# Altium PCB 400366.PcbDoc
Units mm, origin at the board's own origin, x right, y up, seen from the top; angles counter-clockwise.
Board outline 60.96 x 54.86 mm, 4 copper layers (Top Layer, Mid-Layer 1, Mid-Layer 2, Bottom Layer), stack 1.521 mm thick; 27 components, 35 nets, 218 pads, 513 vias.
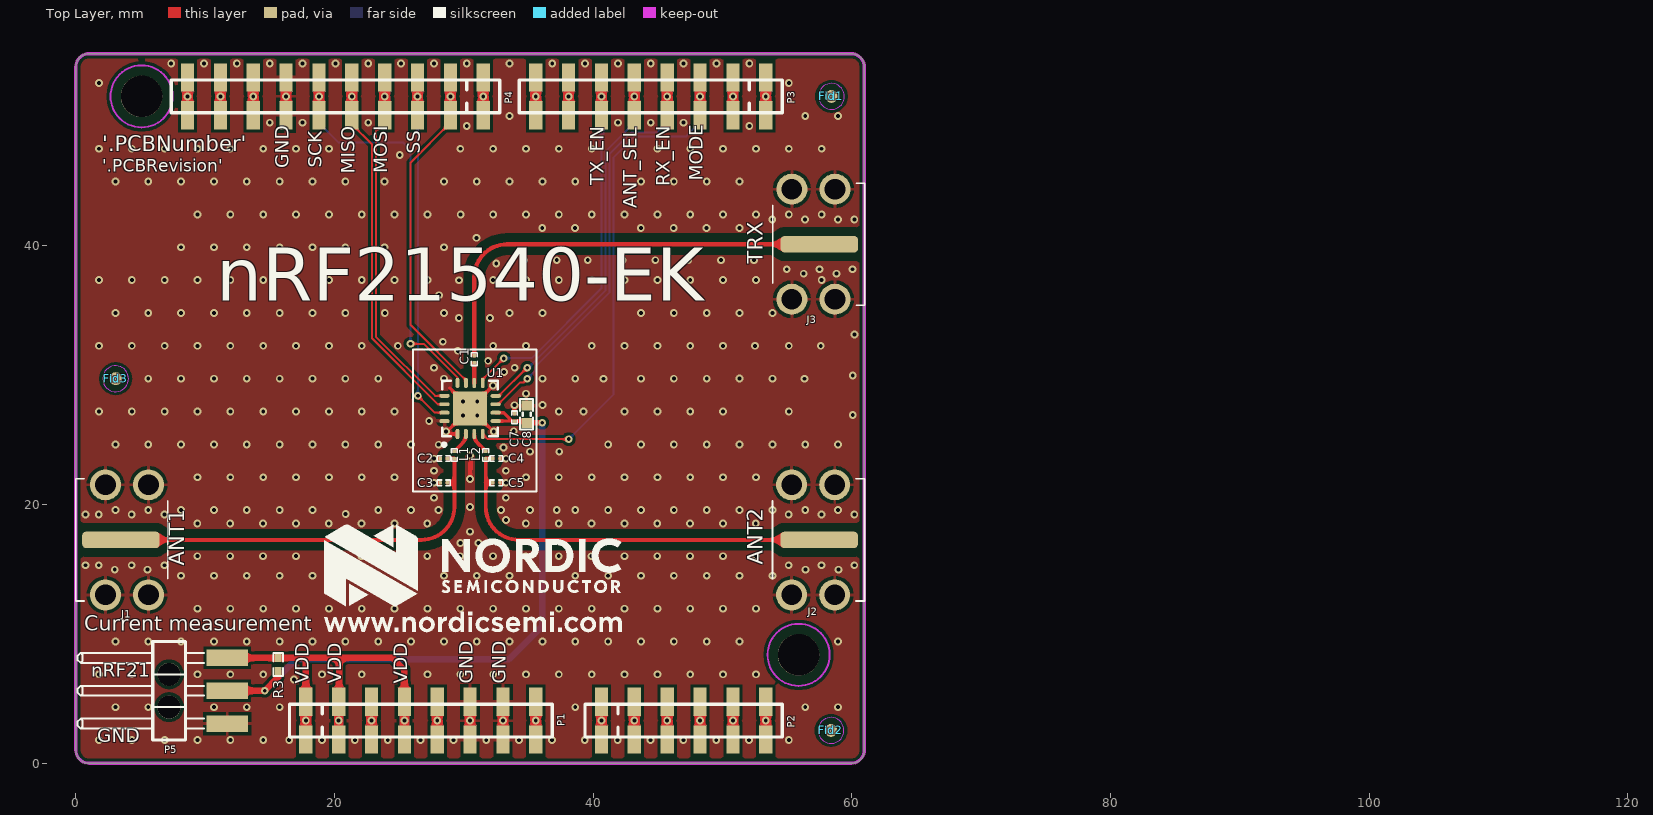
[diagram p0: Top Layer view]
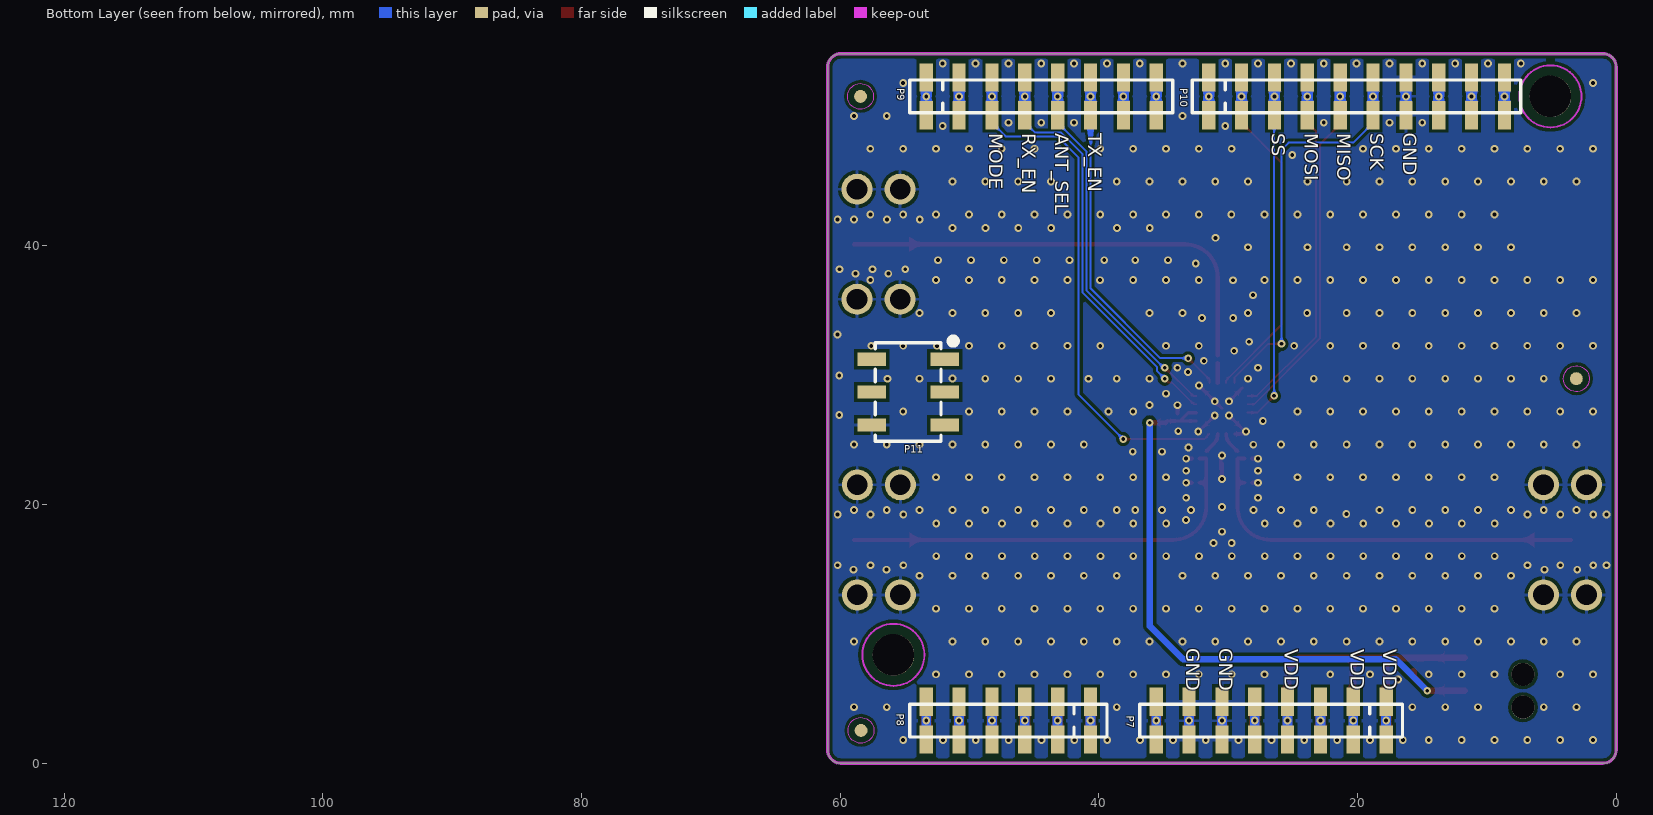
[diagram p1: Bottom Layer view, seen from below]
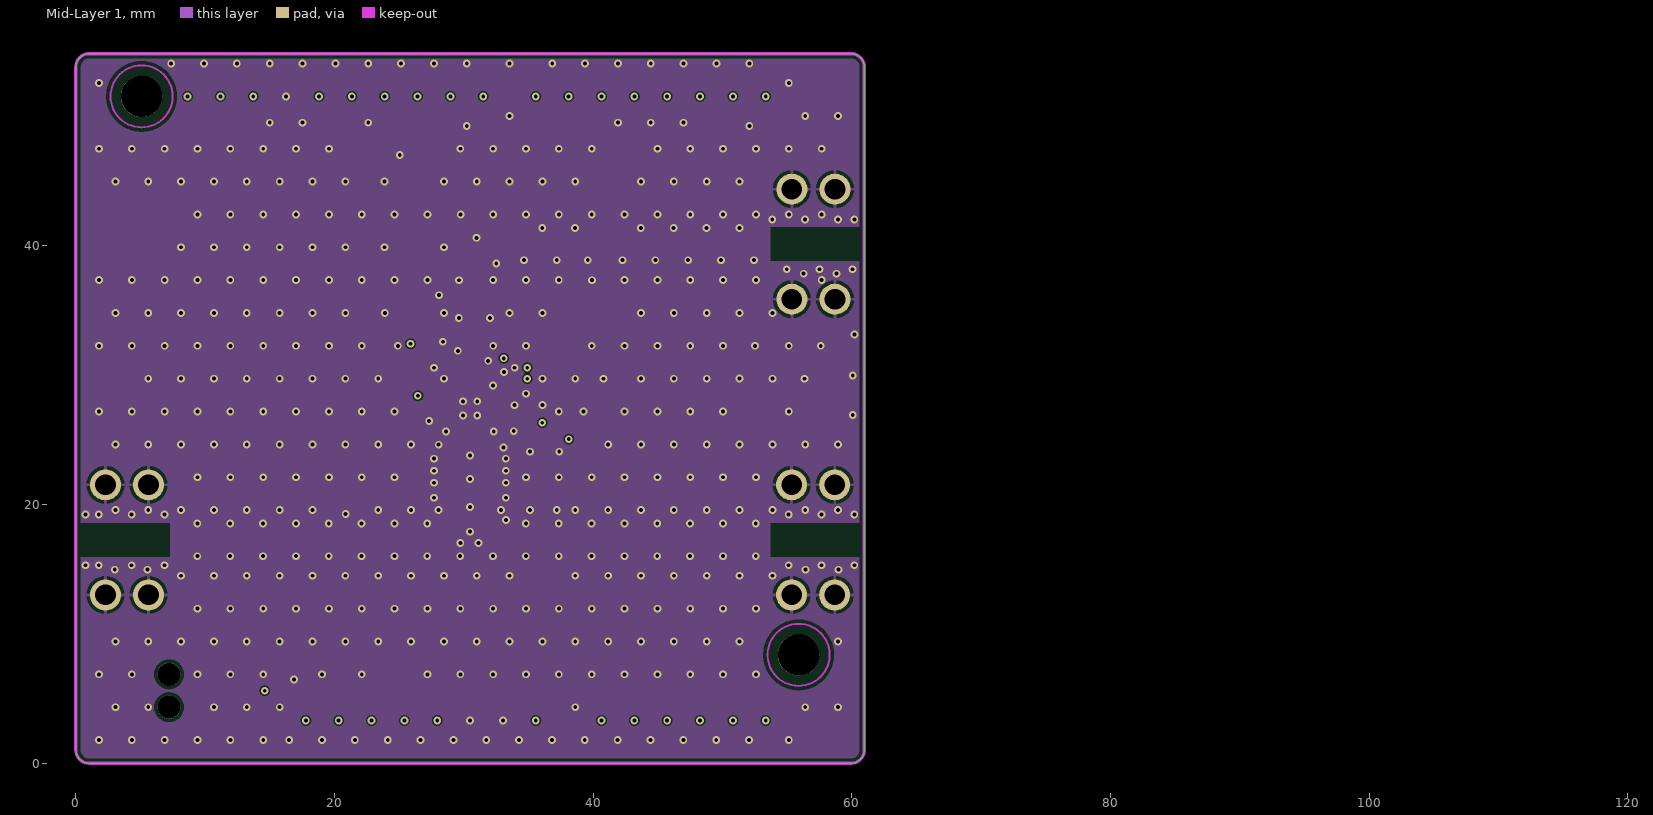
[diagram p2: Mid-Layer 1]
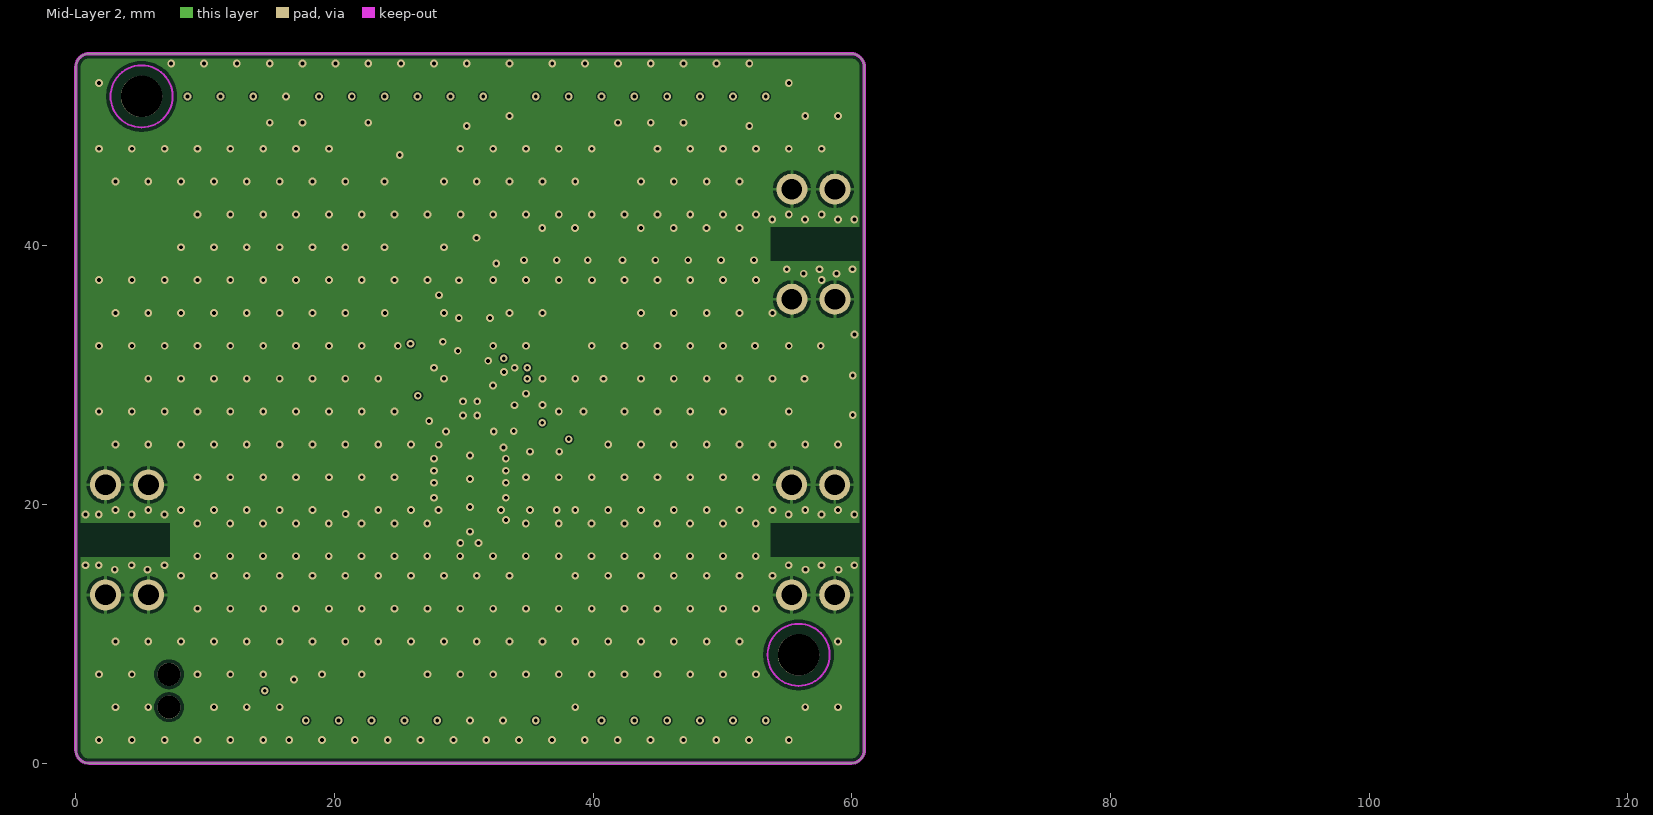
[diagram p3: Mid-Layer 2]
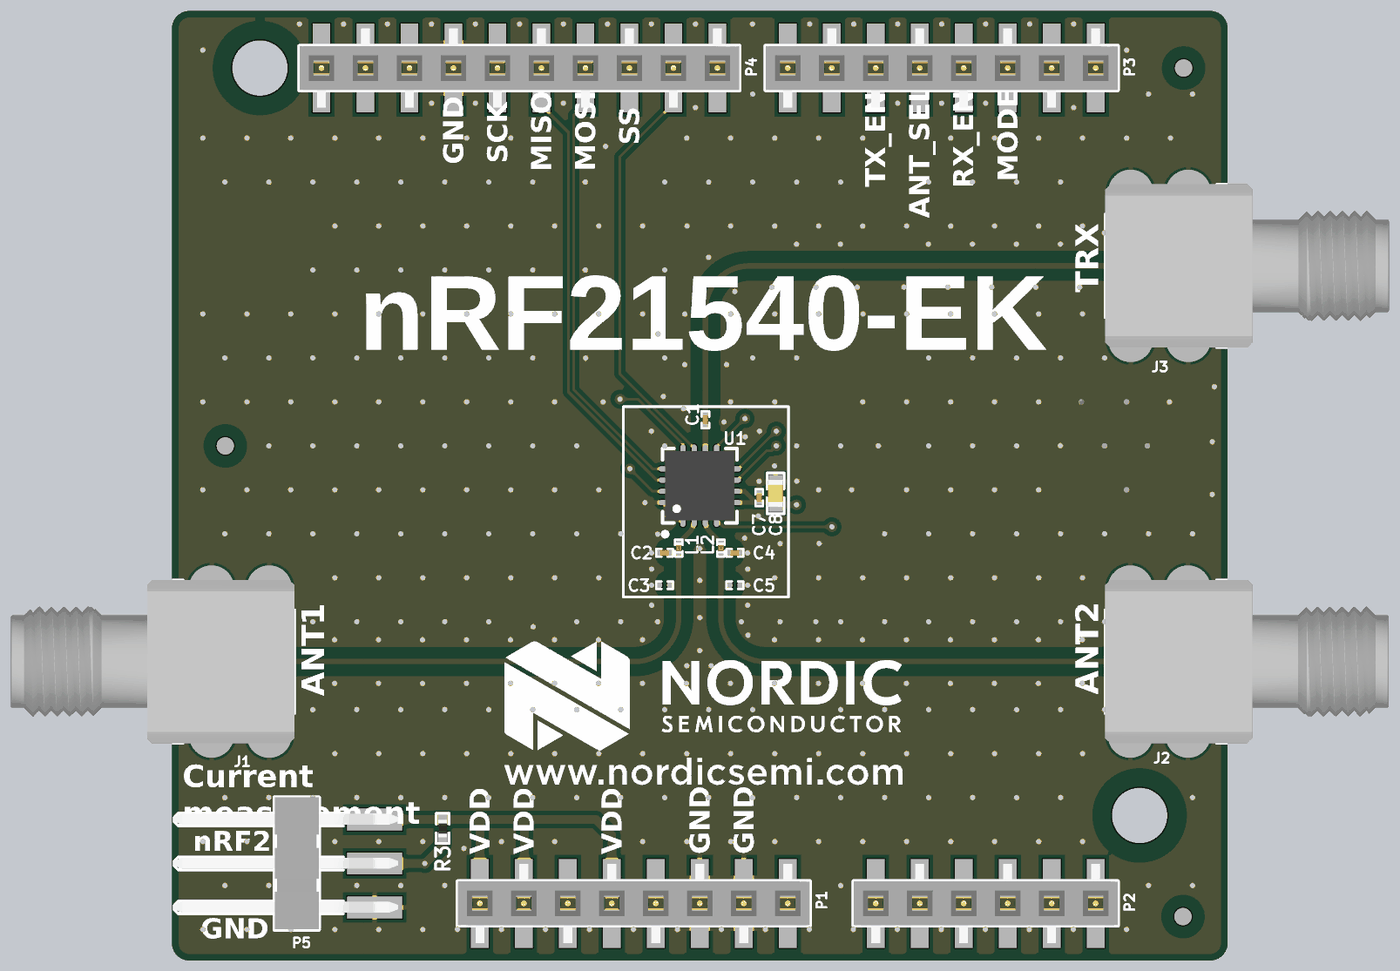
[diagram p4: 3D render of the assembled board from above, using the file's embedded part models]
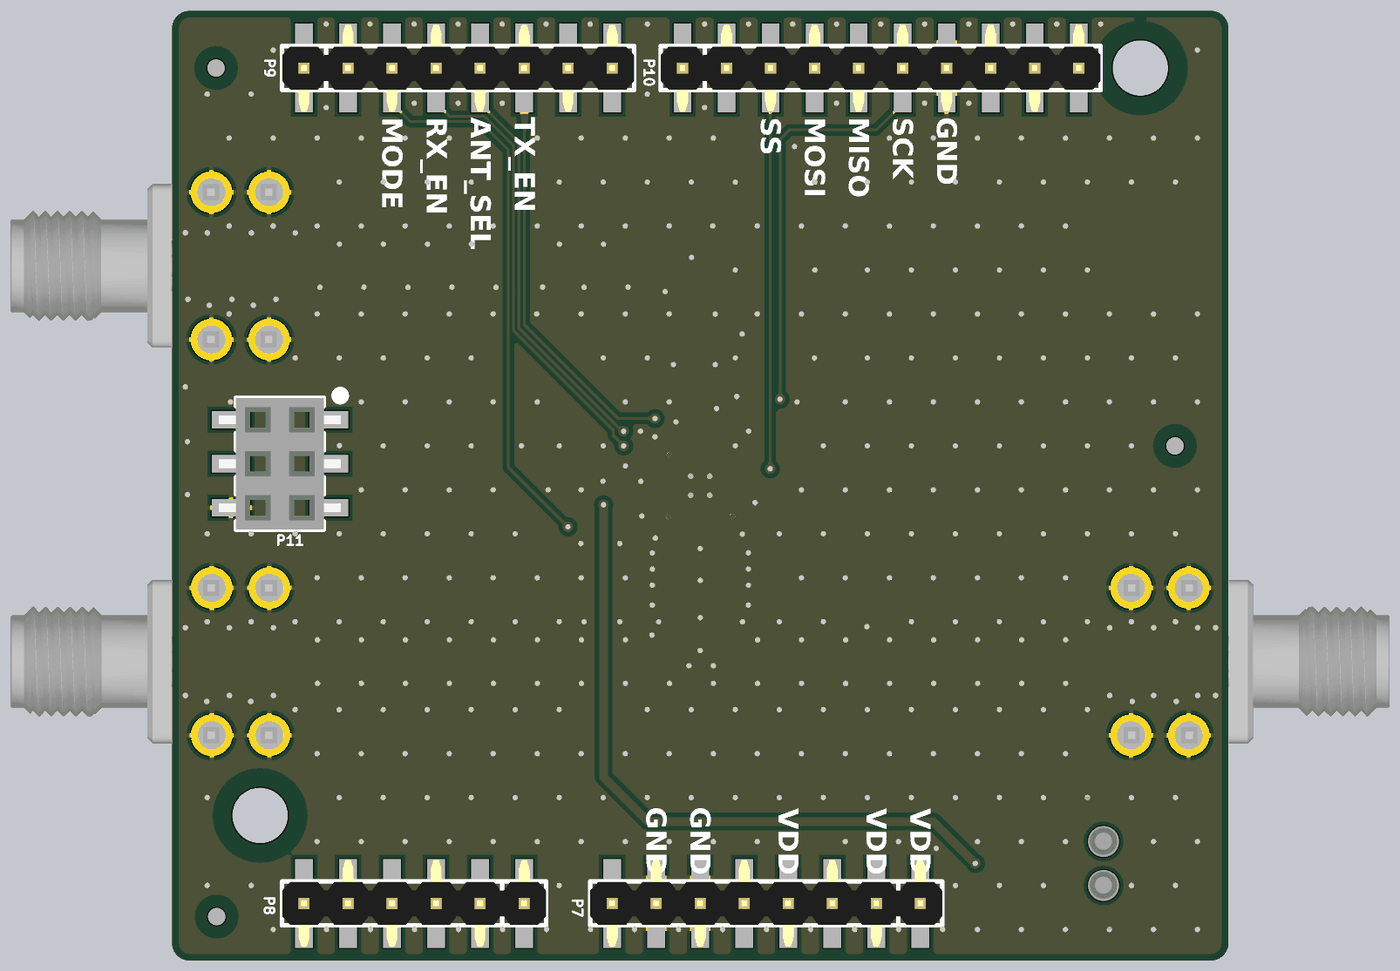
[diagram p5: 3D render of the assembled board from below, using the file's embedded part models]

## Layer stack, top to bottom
Top Solder: solder mask 0.043, SM-003, Dk 3.4
Top Layer: signal copper 0.045
Dielectric1: prepreg 0.166, FR-4, Dk 3.9
Mid-Layer 1: signal copper 0.035
Dielectric2: core 1.029, FR-4, Dk 3.9
Mid-Layer 2: signal copper 0.035
Dielectric3: prepreg 0.166, FR-4, Dk 3.9
Bottom Layer: signal copper 0.045
Bottom Solder: solder mask 0.043, SM-003, Dk 3.4

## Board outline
0,1.016 0,53.848 cw(c1.016,53.848) 1.016,54.864 59.944,54.864 cw(c59.944,53.848) 60.96,53.848 60.96,1.016 cw(c59.944,1.016) 59.944,0 1.016,0 cw(c1.016,1.016)

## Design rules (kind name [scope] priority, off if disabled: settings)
Clearance ANT_Clerance [InNet('ANT1') or InNet('ANT2') or InNet('TRX') or  InNet('RF_O1') or  InNet('RF_O2') or  InNet('RF_I') or  InNet('A') or  InNet('ANT') vs (InNamedPolygon('Top_Layer-GND')) or (InNamedPolygon('Bottom_Layer-GND')) or (InNamedPolygon('Mid_Layer_1-GND')) or (InNamedPolygon('Mid_Layer_2-GND'))] p1: gap=0.7 ignorepadtopadclearanceinfootprint=FALSE
Clearance ANT_Clerance_2 [InNet('ANT11') or  InNet('ANT21') vs (InNamedPolygon('Top_Layer-GND')) or (InNamedPolygon('Bottom_Layer-GND')) or (InNamedPolygon('Mid_Layer_1-GND')) or (InNamedPolygon('Mid_Layer_2-GND'))] p2: gap=0.5 ignorepadtopadclearanceinfootprint=FALSE
Clearance Polygon_Clearance [(InNamedPolygon('Top_Layer-GND')) or (InNamedPolygon('Bottom_Layer-GND')) or (InNamedPolygon('Mid_Layer_1-GND')) or (InNamedPolygon('Mid_Layer_2-GND'))] p3: gap=0.254 ignorepadtopadclearanceinfootprint=FALSE except(0: Arc-Hole Track-Hole SMDPad-Hole THPad-Hole Via-Hole Fill-Hole Poly-Hole Region-Hole Text-Hole)
Clearance [All] p4: gap=0.152 ignorepadtopadclearanceinfootprint=FALSE except(0: Arc-Hole Track-Hole SMDPad-Hole THPad-Hole Via-Hole Fill-Hole Poly-Hole Region-Hole Text-Hole)
ComponentClearance [All] p1 off: gap=0.254 collisioncheckmode=3 verticalgap=0.254 showdistances=FALSE
DiffPairsRouting [All] p1: maxlimit=0.254 minlimit=0.15 mostfreqgap=0.254 toplayer_maxgap=0.15 toplayer_prefgap=0.15 toplayer_minwidth=0.203 toplayer_maxwidth=0.381 toplayer_prefwidth=0.381 midlayer1_mingap=0.254 midlayer1_minwidth=0.203 midlayer1_maxwidth=0.381 midlayer1_prefwidth=0.381 midlayer2_mingap=0.254 midlayer2_minwidth=0.203 midlayer2_maxwidth=0.381 midlayer2_prefwidth=0.381 bottomlayer_maxgap=0.15 bottomlayer_prefgap=0.15 bottomlayer_minwidth=0.203 bottomlayer_maxwidth=0.381 bottomlayer_prefwidth=0.381 maxuncoupledlength=12.7
FabricationTestPointUsage TestPointUsage [All] p1: valid=0 allowmultiple=FALSE
FabricationTestpoint Testpoint [All] p1: side=3 testpointundercomponent=TRUE minsize=1.016 maxsize=2.54 preferedsize=1.524 minholesize=0 maxholesize=1.016 preferedholesize=0.813 testpointgrid=0.025 allowsidetop=TRUE allowsidebottom=TRUE usegrid=TRUE gridtolerance=0
Height [All] p1 off: minheight=0 maxheight=25.4 prefheight=12.7
HoleSize [All] p1: absolutevalues=TRUE maxlimit=5 minlimit=0.3 maxpercent=80.000 minpercent=20.000
MinimumAnnularRing [All] p1 off: minimumring=0.152
MinimumSolderMaskSliver [All] p1: minsoldermaskwidth=0.08
PolygonConnect PolygonConnect_1 [isVia and innet(gnd) or HasFootprint('COAXIAL-SWF')] p1: connectstyle=Direct reliefconductorwidth=0.254 reliefentries=4 polygonreliefangle="90 Angle" airgapwidth=0.254
PolygonConnect [All] p2: connectstyle=Relief reliefconductorwidth=0.254 reliefentries=4 polygonreliefangle="90 Angle" airgapwidth=0.254
RoutingVias [All] p1: holewidth=0.305 width=0.61 viastyle="Through Hole" minholewidth=0.3 minwidth=0.6 maxholewidth=0.711 maxwidth=1.27
SilkToSilkClearance [All] p1: silktosilkclearance=0
SilkToSolderMaskClearance SilkscreenOverComponentPads [IsPad] p1: minsilkscreentomaskgap=0.254 clearancetoexposedcopper=TRUE
SolderMaskExpansion [All] p1: expansion=0.076 istentingtop=FALSE
Width [All] p1: maxlimit=2.54 minlimit=0.152 preferedwidth=0.152
21 further rules are at their usual default settings.

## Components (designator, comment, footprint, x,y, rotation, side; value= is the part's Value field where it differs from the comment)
C1 "1.0pF" CAPC0603X03L_C#1 30.805,31.242 r270 top
C2 "1.2pF" CAPC0603X03L_C#2 28.445,23.557 r0 top
C3 "N.C." CAPC0603X03L_C_NC 28.445,21.684 r0 top
C4 "1.2pF" CAPC0603X03L_C#2 32.508,23.557 r180 top
C5 "N.C." CAPC0603X03L_C_NC 32.508,21.684 r180 top
C7 "100nF" CAPC0603X03L_C#1 33.909,26.747 r270 top
C8 "10µF" CAPC1608X06L 34.857,26.989 r270 top
Fid1 "Fiducial mark" Fiducial 58.42,51.562 r0 top
Fid2 "Fiducial mark" Fiducial 58.385,2.54 r0 top
Fid3 "Fiducial mark" Fiducial 3.08,29.733 r270 top
J1 "SMA_2081005-1" SMA_2081005-1 3.95,17.272 r0 top locked
J2 "SMA_2081005-1" SMA_2081005-1 57.007,17.272 r180 top locked
J3 "SMA_2081005-1" SMA_2081005-1 57.025,40.132 r180 top locked
L1 "1.9nH" INDC0603X03L_C 29.266,23.831 r270 top
L2 "1.9nH" INDC0603X03L_C 31.694,23.831 r270 top
P1 "Socket 1x8" SOCKET_1x8_SMD 17.78,3.302 r0 top locked
P2 "Socket 1x6" SOCKET_1x6_SMD 40.64,3.302 r0 top locked
P3 "Socket 1x8" SOCKET_1x8_SMD 53.34,51.562 r180 top locked
P4 "Socket 1x10" SOCKET_1x10_SMD 31.496,51.562 r180 top locked
P5 "Pin List 1x3, Angled" LIST_ANG_1x3-SMD-2.54MM 11.7,5.607 r270 top locked
P7 "Pin List 1x8" LIST_1x8_SMD 17.78,3.302 r0 bottom locked
P8 "Pin List 1x6" LIST_1x6_SMD 40.64,3.302 r0 bottom locked
P9 "Pin List 1x8" LIST_1x8_SMD 53.34,51.562 r180 bottom locked
P10 "Pin List 1x10" LIST_1x10_SMD 31.496,51.562 r180 bottom locked
P11 "Socket 2x3" SOCKET_2x3_SMD-2.54mm-bottom 54.737,28.702 r270 top locked
R3 "0R" RESC1005X04L 15.635,7.632 r90 top
U1 "nRF21540-QDAA" QFN65P400X400X65_HS-17N 30.48,27.432 r90 top

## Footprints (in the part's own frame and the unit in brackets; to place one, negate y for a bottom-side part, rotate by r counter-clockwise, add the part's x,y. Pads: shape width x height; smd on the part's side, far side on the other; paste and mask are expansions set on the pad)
CAPC0603X03L_C#1 [mm] "Chip Capacitor, 2-Leads, Body 0.6x0.3mm, IPC High Density"
  rect 0.27x0.3 smd: 1(-0.285,0) 2(0.285,0)
  silkscreen extent -0.49,-0.22 0.49,0.22, body extent -0.3,-0.15 0.31,0.15, height 0.3
CAPC0603X03L_C#2 [mm] "Chip Capacitor, 2-Leads, Body 0.6x0.3mm, IPC High Density"
  rrect50% 0.27x0.3 smd: 1(-0.285,0) 2(0.285,0)
  silkscreen extent -0.49,-0.22 0.49,0.22, body extent -0.3,-0.15 0.31,0.15, height 0.3
CAPC0603X03L_C_NC [mm] "Chip Capacitor, 2-Leads, Body 0.6x0.3mm, IPC High Density"
  rrect50% 0.27x0.3 smd: 1(-0.285,0) 2(0.285,0)
  silkscreen extent -0.49,-0.22 0.49,0.22
CAPC1608X06L [mm] "Chip Capacitor, 2-Leads, Body 1.6x0.8mm, IPC High Density"
  rect 0.75x0.8 smd: 1(-0.675,0) 2(0.675,0)
  silkscreen extent -1.17,-0.5 1.17,0.5, body extent -0.8,-0.43 0.8,0.43, height 0.8
Fiducial [mm] "Fiducial Mark"
  round 1 smd: 0(0,0)
  round 1 smd far side: 0(0,0)
  Top Layer keep-out circle w0.01: c0,0 r1
  Bottom Layer keep-out circle w0.01: c0,0 r1
INDC0603X03L_C [mm] "Chip Inductor, 2-Leads, Body 0.6x0.3mm, IPC High Density"
  rrect50% 0.27x0.3 smd: 1(-0.285,0) 2(0.285,0)
  silkscreen extent -0.49,-0.22 0.49,0.22, body extent -0.31,-0.16 0.31,0.16, height 0.26
LIST_1x6_SMD [mm] "Pin List, 2.54mm, SMD"
  rect 1.02x2.19 smd: 1(0,-1.465) 1(0,1.465) 2(2.54,-1.465) 2(2.54,1.465) 3(5.08,-1.465) 3(5.08,1.465) 4(7.62,-1.465) 4(7.62,1.465) 5(10.16,-1.465) 5(10.16,1.465) 6(12.7,-1.465) 6(12.7,1.465)
  silkscreen extent -1.27,-1.27 13.97,1.27, body extent -1.27,-2.5 13.97,2.5, height 9.82
LIST_1x8_SMD [mm] "Pin List, 2.54mm, SMD"
  rect 1.02x2.19 smd: 1(0,-1.465) 1(0,1.465) 2(2.54,-1.465) 2(2.54,1.465) 3(5.08,-1.465) 3(5.08,1.465) 4(7.62,-1.465) 4(7.62,1.465) 5(10.16,-1.465) 5(10.16,1.465) 6(12.7,-1.465) 6(12.7,1.465) 7(15.24,-1.465) 7(15.24,1.465) 8(17.78,-1.465) 8(17.78,1.465)
  silkscreen extent -1.27,-1.27 19.05,1.27, body extent -1.27,-2.5 19.05,2.5, height 9.82
LIST_1x10_SMD [mm] "Pin List, 2.54mm, SMD"
  rect 1.02x2.19 smd: 1(0,-1.465) 1(0,1.465) 2(2.54,-1.465) 2(2.54,1.465) 3(5.08,-1.465) 3(5.08,1.465) 4(7.62,-1.465) 4(7.62,1.465) 5(10.16,-1.465) 5(10.16,1.465) 6(12.7,-1.465) 6(12.7,1.465) 7(15.24,-1.465) 7(15.24,1.465) 8(17.78,-1.465) 8(17.78,1.465) 9(20.32,-1.465) 9(20.32,1.465) 10(22.86,-1.465) 10(22.86,1.465)
  silkscreen extent -1.27,-1.27 24.13,1.27, body extent -1.27,-2.5 24.13,2.5, height 9.82
LIST_ANG_1x3-SMD-2.54MM [mm] "Pin List, 2.54mm, Surface Mount, Angled"
  round 1.78 hole 1.78 unplated: 0(-1.27,-4.496) 0(1.27,-4.496)
  rect 1.27x3.18 smd: 1(-2.54,0) 2(0,0) 3(2.54,0)
  silkscreen extent -3.81,-11.58 3.81,-1.8, body extent -3.83,-11.61 3.79,1.35, height 3.03
QFN65P400X400X65_HS-17N [mm] "QFN, 16-Leads, Body 4.00x4.00mm, Pitch 0.65mm, Thermal Pad 2.65x2.65mm, IPC Medium Density"
  oval 0.8x0.3 smd: 1(-1.975,0.975) 2(-1.975,0.325) 3(-1.975,-0.325) 4(-1.975,-0.975) 9(1.975,-0.975) 10(1.975,-0.325) 11(1.975,0.325) 12(1.975,0.975)
  oval 0.3x0.8 smd: 5(-0.975,-1.975) 6(-0.325,-1.975) 7(0.325,-1.975) 8(0.975,-1.975) 13(0.975,1.975) 14(0.325,1.975) 15(-0.325,1.975) 16(-0.975,1.975)
  rect 2.65x2.65 smd: 17(0,0)
  silkscreen extent -2.92,-2.15 2.15,2.15, body extent -2,-2 2,2, height 0.65
RESC1005X04L [mm] "Chip Resistor, 2-Leads, Body 1.0x0.5mm, IPC High Density"
  rect 0.6x0.55 smd: 1(-0.5,0) 2(0.5,0)
  silkscreen extent -0.87,-0.38 0.88,0.38, body extent -0.5,-0.25 0.5,0.25, height 0.3
SMA_2081005-1 [mm] "SMA, Right Angle, Board Edge, TH/SMT mount, 50Ohm"
  round 2.6 on Top Paste: 0(-1.665,-4.255) 0(-1.665,4.255) 0(1.665,-4.255) 0(1.665,4.255)
  rrect50% 6x1.27 smd: 1(-0.465,0)
  round 2.4 hole 1.6: 2(-1.665,-4.255) 2(-1.665,4.255) 2(1.665,-4.255) 2(1.665,4.255)
  silkscreen extent -3.97,-4.72 3.15,4.72, body extent -13.25,-4.72 3.13,4.72, height 6.37
SOCKET_1x6_SMD [mm] "Socket, 2.54mm, SMD"
  rect 1.02x2.19 smd: 1(0,-1.465) 1(0,1.465) 2(2.54,-1.465) 2(2.54,1.465) 3(5.08,-1.465) 3(5.08,1.465) 4(7.62,-1.465) 4(7.62,1.465) 5(10.16,-1.465) 5(10.16,1.465) 6(12.7,1.465) 6(12.7,-1.465)
  silkscreen extent -1.27,-1.27 13.97,1.27, body extent -1.27,-2.29 13.97,2.29, height 7.47
SOCKET_1x8_SMD [mm] "Socket, 2.54mm, SMD"
  rect 1.02x2.19 smd: 1(0,-1.465) 1(0,1.465) 2(2.54,-1.465) 2(2.54,1.465) 3(5.08,-1.465) 3(5.08,1.465) 4(7.62,-1.465) 4(7.62,1.465) 5(10.16,-1.465) 5(10.16,1.465) 6(12.7,1.465) 6(12.7,-1.465) 7(15.24,-1.465) 7(15.24,1.465) 8(17.78,-1.465) 8(17.78,1.465)
  silkscreen extent -1.27,-1.27 19.05,1.27, body extent -1.27,-2.29 19.05,2.29, height 7.47
SOCKET_1x10_SMD [mm] "Socket, 2.54mm, SMD"
  rect 1.02x2.19 smd: 1(0,1.465) 1(0,-1.465) 2(2.54,-1.465) 2(2.54,1.465) 3(5.08,-1.465) 3(5.08,1.465) 4(7.62,-1.465) 4(7.62,1.465) 5(10.16,-1.465) 5(10.16,1.465) 6(12.7,-1.465) 6(12.7,1.465) 7(15.24,-1.465) 7(15.24,1.465) 8(17.78,-1.465) 8(17.78,1.465) 9(20.32,-1.465) 9(20.32,1.465) 10(22.86,-1.465) 10(22.86,1.465)
  silkscreen extent -1.27,-1.27 24.13,1.27, body extent -1.27,-2.29 24.13,2.29, height 7.47
SOCKET_2x3_SMD-2.54mm-bottom [mm] "Socket, 2.54mm, SMD"
  rect 1.02x2.22 smd far side: 1(-2.54,-2.825) 2(-2.54,2.825) 3(0,-2.825) 4(0,2.825) 5(2.54,-2.825) 6(2.54,2.825)
  body extent -3.81,-3.52 3.81,3.52, height 7.47

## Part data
C1: library part C0201-1p0, "CAP CER 1PF 25V C0G/NP0 0201", Manufacturer=Murata, Manufacturer Part Number=GJM0335C1E1R0BB01D, Part number IPS=N.A., Supplier Part Number 1=490-11172-1-ND
C2 C4: library part C0201-1.2p, "Chip Cap 0201", Part number IPS=N.A.
C3 C5: library part C0201-N.C., "Not mounted", Part number IPS=N.A.
C7: library part C0201-100n, "Capacitor, X5R, ±10%", Part number IPS="00000001248, 00000002505"
C8: library part C0603-10µ, "Capacitor, X5R, ±20%", Part number IPS=00000007785
Fid1 Fid2 Fid3: library part Fid-Mark, "Fiducial Mark", Part number IPS=N.A.
J1 J2 J3: library part SMA_RA_EDGE_SMT, "SMA, Female, Right Angle, TH/SMT, 50Ohm, Board Edge", Manufacturer=CompuPack, Manufacturer Part Number=ARFRBE22029-GGP, Part number IPS=N.A., Supplier Part Number 1=C-Q1911001
L1 L2: library part L0201-1n9-HQ-Murata, "Inductor, 600mA, ±0.1ｎH, 120mOhm", Manufacturer=Murata, Manufacturer Part Number=LQP03HQ1N9B02, Part number IPS=N.A., Supplier Part Number 1=490-13889-1-ND
P1 P3: library part "Socket 1x8 SMD", "Socket 1x8, 2.54mm (100mil), SMD", Manufacturer=W-CON, Manufacturer Part Number=2171-108MS0CUNR1, Part number IPS=00000009963
P2: library part "Socket 1x6 SMD", "Socket 1x6, 2.54mm (100mil), SMD", Manufacturer=W-CON, Manufacturer Part Number=2171-106MS0CUNR1, Part number IPS=00000009964
P4: library part "Socket 1x10 SMD", "Socket 1x10, 2.54mm (100mil), SMD", Manufacturer=W-CON, Manufacturer Part Number=2171-110MS0CUNR1, Part number IPS=00000009965
P5: library part "Pin List Ang 1x3 SMD, 2.54mm", "Pin List 1x3, 2.54mm (100mil), Right Angled, SMD", Manufacturer=W-CON, Manufacturer Part Number=1125B-1103S0Z135R2, Part number IPS=00000009971
P7 P9: library part "Pin List 1x8 SMD", "Pin List 1x8, 2.54mm (100mil), SMD", Manufacturer=W-CON, Manufacturer Part Number=1125-1108S0M116R2, Part number IPS=N.A.
P8: library part "Pin List 1x6 SMD", "Pin List 1x6, 2.54mm (100mil), SMD", Manufacturer=W-CON, Manufacturer Part Number=1125-1106S0M116R2, Part number IPS=N.A.
P10: library part "Pin List 1x10 SMD", "Pin List 1x10, 2.54mm (100mil), SMD", Manufacturer=W-CON, Manufacturer Part Number=1125-1110S0M116R2, Part number IPS=N.A.
P11: library part "Socket 2x3 SMD Bottom", "Socket 2x3, 2.54mm (100mil), SMD", Manufacturer=W-CON, Manufacturer Part Number=2171-203MS0CUNR1, Part number IPS=N.A.
R3: library part R0402-0R, "Resistor, ±5%, 0.063W", Part number IPS=00000007128, Supplier Part Number 1=146-9661
U1: "Radio front-end / range extender for 2.4GHz", Manufacturer="Nordic Semiconductor", Part number IPS=N.A.

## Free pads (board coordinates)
  round 3.2 hole 3.2 unplated: 1(5.08,51.562) 1(55.88,8.382)
  round 0.3 on Mech16: 1(117.207,34.156) 1(118.957,35.906) 1(118.957,36.406) 1(118.957,36.906) 1(118.957,37.406) 1(118.957,37.906) 1(118.957,38.407)

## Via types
v1: diameter 0.6, hole 0.3, Top Layer to Bottom Layer, tented both sides, 513 vias

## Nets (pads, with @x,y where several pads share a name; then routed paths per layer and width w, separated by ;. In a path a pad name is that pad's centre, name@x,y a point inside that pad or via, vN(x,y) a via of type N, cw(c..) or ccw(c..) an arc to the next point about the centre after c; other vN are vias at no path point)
A0: P2.1 P8.1 | length 5.9
  Top Layer w0.762: P2.1@40.64,1.837 P2.1@40.64,4.767
  Bottom Layer w0.762: P8.1@40.64,1.837 v1(40.64,3.302) P8.1@40.64,4.767
A1: P2.2 P8.2 | length 5.9
  Top Layer w0.762: P2.2@43.18,1.837 P2.2@43.18,4.767
  Bottom Layer w0.762: P8.2@43.18,1.837 v1(43.18,3.302) P8.2@43.18,4.767
A2: P2.3 P8.3 | length 5.9
  Top Layer w0.762: P2.3@45.72,1.837 P2.3@45.72,4.767
  Bottom Layer w0.762: P8.3@45.72,1.837 v1(45.72,3.302) P8.3@45.72,4.767
A3: P2.4 P8.4 | length 5.9
  Top Layer w0.762: P2.4@48.26,1.837 P2.4@48.26,4.767
  Bottom Layer w0.762: P8.4@48.26,1.837 v1(48.26,3.302) P8.4@48.26,4.767
A4: P2.5 P8.5 | length 5.9
  Top Layer w0.762: P2.5@50.8,1.837 P2.5@50.8,4.767
  Bottom Layer w0.762: P8.5@50.8,1.837 v1(50.8,3.302) P8.5@50.8,4.767
A5: P2.6 P8.6 | length 5.9
  Top Layer w0.762: P2.6@53.34,1.837 P2.6@53.34,4.767
  Bottom Layer w0.762: P8.6@53.34,1.837 v1(53.34,3.302) P8.6@53.34,4.767
ANT1: L1.1 U1.2 | length 1.7
  Top Layer w0.28: L1.1 29.835,24.685 ccw(c29.063,25.457) U1.2
ANT2: L2.1 U1.3 | length 1.7
  Top Layer w0.28: U1.3 ccw(c31.896,25.457) 31.125,24.685 L2.1
ANT_SEL: P3.5 P9.5 U1.8 | length 32.2
  Top Layer w0.152: U1.8 32.705,28.407 34.88,30.582 v1(34.901,30.582)
  Top Layer w0.762: P3.5@43.18,50.097 P3.5@43.18,53.027
  Bottom Layer w0.152: v1(34.901,30.582) 34.991,30.582 40.945,36.536 40.945,47.295 43.18,49.53 P9.5@43.18,50.097
  Bottom Layer w0.762: P9.5@43.18,50.097 P9.5@43.18,53.027
  other v1: 43.18,51.562
AREF: P4.8 P10.8 | length 5.9
  Top Layer w0.762: P4.8@13.716,50.097 P4.8@13.716,53.027
  Bottom Layer w0.762: P10.8@13.716,50.097 P10.8@13.716,53.027
  other v1: 13.716,51.562
"D0 (RX)": P3.1 P9.1 | length 5.9
  Top Layer w0.762: P3.1@53.34,50.097 P3.1@53.34,53.027
  Bottom Layer w0.762: P9.1@53.34,50.097 P9.1@53.34,53.027
  other v1: 53.34,51.562
"D1 (TX)": P3.2 P9.2 | length 5.9
  Top Layer w0.762: P3.2@50.8,50.097 P3.2@50.8,53.027
  Bottom Layer w0.762: P9.2@50.8,50.097 P9.2@50.8,53.027
  other v1: 50.8,51.562
D6: P3.7 P9.7 | length 5.9
  Top Layer w0.762: P3.7@38.1,50.097 P3.7@38.1,53.027
  Bottom Layer w0.762: P9.7@38.1,50.097 P9.7@38.1,53.027
  other v1: 38.1,51.562
D7: P3.8 P9.8 | length 6.4
  Top Layer w0.762: P3.8@35.56,50.097 P3.8@35.56,53.027
  Bottom Layer w0.152: P9.8@35.56,49.53 P9.8@35.56,50.097
  Bottom Layer w0.762: P9.8@35.56,50.097 P9.8@35.56,53.027
  other v1: 35.56,51.562
D8: P4.1 P10.1 | length 5.9
  Top Layer w0.762: P4.1@31.496,50.097 P4.1@31.496,53.027
  Bottom Layer w0.762: P10.1@31.496,50.097 P10.1@31.496,53.027
  other v1: 31.496,51.562
"D10 (SS)": P4.3 P10.3 U1.15 | length 30.1
  Top Layer w0.152: v1(26.441,28.411) 27.746,27.107 U1.15
  Top Layer w0.762: P4.3@26.416,50.097 P4.3@26.416,53.027
  Bottom Layer w0.152: v1(26.441,28.411) P10.3@26.441,50.072
  Bottom Layer w0.762: P10.3@26.416,50.097 P10.3@26.416,53.027
  other v1: 26.416,51.562
"D11 (MOSI)": P4.4 P10.4 U1.13 | length 29.9
  Top Layer w0.152: P4.4@23.876,49.53 23.203,48.857 23.203,32.981 27.776,28.407 U1.13
  Top Layer w0.762: P4.4@23.876,50.097 P4.4@23.876,53.027
  Bottom Layer w0.762: P10.4@23.876,50.097 P10.4@23.876,53.027
  other v1: 23.876,51.562
"D12 (MISO)": P4.5 P10.5 U1.14 | length 30.8
  Top Layer w0.152: P4.5@21.336,49.408 22.898,47.847 22.898,32.854 27.995,27.757 U1.14
  Top Layer w0.762: P4.5@21.336,50.097 P4.5@21.336,53.027
  Bottom Layer w0.762: P10.5@21.336,50.097 P10.5@21.336,53.027
  other v1: 21.336,51.562
"D13 (SCK)": P4.6 P10.6 U1.12 | length 34
  Top Layer w0.152: v1(25.872,32.432) 26.902,32.432 29.505,29.829 U1.12
  Top Layer w0.762: P4.6@18.796,50.097 P4.6@18.796,53.027
  Bottom Layer w0.152: P10.6@18.796,49.53 18.796,49.512 20.317,47.991 25.315,47.991 25.872,47.434 v1(25.872,32.432)
  Bottom Layer w0.762: P10.6@18.796,50.097 P10.6@18.796,53.027
  other v1: 18.796,51.562
GND: C2.1 C3.1 C4.1 C5.1 C7.1 C8.1 J1.2 J2.2 J3.2 P1.6 P1.7 P4.7 P5.3 P7.6 P7.7 P10.7 P11.6 U1.1 U1.16 U1.17 | length 28.6
  Top Layer w0.254: v1@28.823,25.457 U1.1 ; 28.894,25.846 v1(29.93,26.882) ; 28.894,29.018 v1(29.93,27.982) ; U1.17 v1(31.03,27.982) v1@32.066,29.018 ; v1(31.03,26.882) 32.066,25.846
  Top Layer w0.3: v1(27.7,23.55) 27.707,23.557 C2.1 ; v1@27.707,21.684 C3.1 ; v1(30.48,21.971) 30.48,23.177 ; C5.1 v1@33.247,21.684 ; C4.1 v1@33.247,23.557 ; C7.1 v1(33.909,27.686)
  Top Layer w0.762: P4.7@16.256,50.097 P4.7@16.256,53.027 ; P1.6@30.48,1.837 P1.6@30.48,4.767 ; P1.7@33.02,1.837 P1.7@33.02,4.767
  Bottom Layer w0.762: P10.7@16.256,50.097 P10.7@16.256,53.027 ; P7.6@30.48,1.837 v1(30.48,3.302) P7.6@30.48,4.767 ; P7.7@33.02,1.837 v1(33.02,3.302) P7.7@33.02,4.767
  other v1: 1.785,1.795 4.325,1.795 6.865,1.795 9.405,1.795 11.945,1.795 14.485,1.795 16.49,1.8 19.03,1.8 21.57,1.8 24.11,1.8 26.65,1.8 29.19,1.8 31.73,1.8 34.27,1.8 36.81,1.8 39.35,1.8 41.89,1.8 44.43,1.8 46.97,1.8 49.51,1.8 52.05,1.8 55.125,1.795 3.055,4.335 5.595,4.335 10.675,4.335 13.215,4.335 15.755,4.335 38.615,4.335 56.395,4.335 58.935,4.335 16.857,6.483 1.785,6.875 4.325,6.875 9.405,6.875 11.945,6.875 14.485,6.875 19.03,6.875 22.105,6.875 27.185,6.875 29.725,6.875 32.265,6.875 34.805,6.875 37.345,6.875 39.885,6.875 42.425,6.875 44.965,6.875 47.505,6.875 50.045,6.875 52.585,6.875 3.055,9.415 5.595,9.415 8.135,9.415 10.675,9.415 13.215,9.415 15.755,9.415 18.295,9.415 20.835,9.415 23.375,9.415 25.915,9.415 28.455,9.415 30.995,9.415 33.535,9.415 36.075,9.415 38.615,9.415 41.155,9.415 43.695,9.415 46.235,9.415 48.775,9.415 51.315,9.415 58.935,9.415 9.405,11.955 11.945,11.955 14.485,11.955 17.025,11.955 19.565,11.955 22.105,11.955 24.645,11.955 27.185,11.955 29.725,11.955 32.265,11.955 34.805,11.955 37.345,11.955 39.885,11.955 42.425,11.955 44.965,11.955 47.505,11.955 50.045,11.955 52.585,11.955 8.135,14.495 10.675,14.495 13.215,14.495 15.755,14.495 18.295,14.495 20.835,14.495 23.375,14.495 25.915,14.495 28.455,14.495 30.995,14.495 33.535,14.495 38.615,14.495 41.155,14.495 43.695,14.495 46.235,14.495 48.775,14.495 51.315,14.495 53.855,14.495 3.003,14.97 5.543,14.97 56.42,14.97 58.96,14.97 0.738,15.314 1.772,15.314 4.312,15.314 6.852,15.314 55.112,15.314 57.652,15.314 60.192,15.314 9.392,16.014 11.932,16.014 14.472,16.014 17.012,16.014 19.552,16.014 22.092,16.014 24.632,16.014 27.172,16.014 29.712,16.014 32.252,16.014 34.792,16.014 37.332,16.014 39.872,16.014 42.412,16.014 44.952,16.014 47.492,16.014 50.032,16.014 52.572,16.014 29.725,17.035 31.136,17.033 30.48,17.907 9.392,18.529 11.932,18.529 14.472,18.529 17.012,18.529 19.552,18.529 22.092,18.529 24.632,18.529 27.172,18.529 34.792,18.529 37.332,18.529 39.872,18.529 42.412,18.529 44.952,18.529 47.492,18.529 50.032,18.529 52.572,18.529 33.261,18.799 0.738,19.229 1.772,19.229 4.312,19.229 6.852,19.229 55.112,19.229 57.652,19.229 60.192,19.229 20.86,19.28 3.055,19.575 5.595,19.575 8.135,19.575 10.675,19.575 13.215,19.575 15.755,19.575 18.295,19.575 23.375,19.575 25.915,19.575 28.041,19.572 32.88,19.572 35.117,19.572 37.184,19.572 38.615,19.575 41.155,19.575 43.695,19.575 46.235,19.575 48.775,19.575 51.315,19.575 53.855,19.575 56.395,19.575 58.935,19.575 30.48,19.812 27.7,20.532 33.243,20.532 27.7,21.684 33.243,21.684 9.405,22.115 11.945,22.115 14.485,22.115 17.025,22.115 19.565,22.115 22.105,22.115 24.645,22.115 34.805,22.115 37.345,22.115 39.885,22.115 42.425,22.115 44.965,22.115 47.505,22.115 50.045,22.115 52.585,22.115 27.7,22.617 33.243,22.617 33.243,23.55 30.48,23.802 35.117,24.09 37.37,24.09 33.068,24.407 28.05,24.632 3.055,24.655 5.595,24.655 8.135,24.655 10.675,24.655 13.215,24.655 15.755,24.655 18.295,24.655 20.835,24.655 23.375,24.655 25.915,24.655 41.155,24.655 43.695,24.655 46.235,24.655 48.775,24.655 51.315,24.655 53.855,24.655 56.395,24.655 58.935,24.655 28.626,25.654 32.309,25.654 33.858,25.679 27.317,26.457 60.071,26.924 1.785,27.195 4.325,27.195 6.865,27.195 9.405,27.195 11.945,27.195 14.485,27.195 17.025,27.195 19.565,27.195 22.105,27.195 24.645,27.195 37.345,27.195 39.252,27.194 42.425,27.195 44.965,27.195 47.505,27.195 50.045,27.195 55.125,27.195 36.085,27.692 34.798,28.575 32.258,29.21 5.595,29.735 8.135,29.735 10.675,29.735 13.215,29.735 15.755,29.735 18.295,29.735 20.835,29.735 23.375,29.735 28.455,29.735 36.075,29.735 38.615,29.735 40.792,29.734 43.695,29.735 46.235,29.735 48.775,29.735 53.855,29.735 56.328,29.734 51.302,29.743 60.071,29.972 33.096,30.251 27.686,30.582 33.927,30.582 31.877,31.115 29.534,31.889 1.785,32.275 4.325,32.275 6.865,32.275 9.405,32.275 11.945,32.275 14.485,32.275 17.025,32.275 19.565,32.275 22.105,32.275 24.895,32.275 32.265,32.275 34.805,32.275 39.885,32.275 42.425,32.275 44.965,32.275 47.505,32.275 50.045,32.275 52.518,32.274 55.125,32.275 57.598,32.274 28.372,32.588 60.198,33.147 29.61,34.429 32.023,34.429 3.055,34.815 5.595,34.815 8.135,34.815 10.675,34.815 13.215,34.815 15.755,34.815 18.295,34.815 20.835,34.815 23.89,34.807 28.455,34.815 33.535,34.815 36.075,34.815 43.695,34.815 46.235,34.815 48.775,34.815 51.315,34.815 53.855,34.815 28.067,36.195 1.785,37.355 4.325,37.355 6.865,37.355 9.405,37.355 11.945,37.355 14.485,37.355 17.025,37.355 19.565,37.355 22.105,37.355 24.645,37.355 27.185,37.355 29.615,37.35 32.265,37.355 34.805,37.355 37.345,37.355 39.91,37.353 42.425,37.355 44.965,37.355 47.505,37.355 50.045,37.355 52.585,37.355 57.665,37.355 56.272,37.855 58.812,37.855 54.964,38.199 57.504,38.199 60.044,38.199 32.506,38.645 34.644,38.899 37.184,38.899 39.574,38.899 42.264,38.899 44.804,38.899 47.344,38.899 49.884,38.899 52.424,38.899 8.135,39.895 10.675,39.895 13.215,39.895 15.755,39.895 18.295,39.895 20.835,39.895 23.865,39.895 28.455,39.895 30.982,40.627 36.062,41.389 38.602,41.389 43.682,41.389 46.222,41.389 48.762,41.389 51.302,41.389 53.842,42.039 56.382,42.039 58.922,42.039 60.192,42.049 9.405,42.435 11.945,42.435 14.485,42.435 17.025,42.435 19.565,42.435 22.105,42.435 24.645,42.435 27.185,42.435 29.75,42.435 32.265,42.435 34.805,42.435 37.345,42.435 39.885,42.435 42.425,42.435 44.965,42.435 47.505,42.435 50.045,42.435 52.585,42.435 55.125,42.435 57.665,42.435 3.055,44.975 5.595,44.975 8.135,44.975 10.675,44.975 13.215,44.975 15.755,44.975 18.295,44.975 20.835,44.975 23.865,44.975 28.455,44.975 30.995,44.975 33.535,44.975 36.075,44.975 38.615,44.975 43.695,44.975 46.235,44.975 48.775,44.975 51.315,44.975 25.04,47.032 1.785,47.515 4.325,47.515 6.865,47.515 9.405,47.515 11.945,47.515 14.485,47.515 17.025,47.515 19.565,47.515 29.725,47.515 32.265,47.515 34.805,47.515 37.345,47.515 39.885,47.515 44.965,47.515 47.505,47.515 50.045,47.515 52.585,47.515 55.125,47.515 57.665,47.515 30.226,49.276 52.07,49.276 14.986,49.53 17.526,49.53 22.606,49.53 41.91,49.53 44.45,49.53 46.99,49.53 33.535,50.055 56.395,50.055 58.935,50.055 16.256,51.562 1.785,52.595 55.125,52.595 7.366,54.102 9.906,54.102 12.446,54.102 14.986,54.102 17.526,54.102 20.066,54.102 22.606,54.102 25.146,54.102 27.686,54.102 30.226,54.102 33.528,54.102 36.83,54.102 39.37,54.102 41.91,54.102 44.45,54.102 46.99,54.102 49.53,54.102 52.07,54.102
MODE: P3.3 P9.3 U1.4 | length 44.3
  Top Layer w0.152: U1.4 31.855,25.057 v1(38.113,25.057)
  Top Layer w0.762: P3.3@48.26,50.097 P3.3@48.26,53.027
  Bottom Layer w0.152: v1(38.113,25.057) 41.554,28.499 41.554,46.831 43.192,48.469 47.199,48.469 48.26,49.53 P9.3@48.26,50.097
  Bottom Layer w0.762: P9.3@48.26,50.097 P9.3@48.26,53.027
  other v1: 48.26,51.562
NetP1_5: P1.5 P7.5 | length 5.9
  Top Layer w0.762: P1.5@27.94,1.837 P1.5@27.94,4.767
  Bottom Layer w0.762: P7.5@27.94,1.837 v1(27.94,3.302) P7.5@27.94,4.767
NetP1_8: P1.8 P7.8 | length 5.9
  Top Layer w0.762: P1.8@35.56,1.71 P1.8@35.56,4.64
  Bottom Layer w0.762: P7.8@35.56,1.837 v1(35.56,3.302) P7.8@35.56,4.767
PDN: P4.2 P10.2 U1.11 | length 29.6
  Top Layer w0.152: P4.2@28.956,50.097 28.956,49.512 25.872,46.428 25.872,33.894 30.155,29.61 U1.11
  Top Layer w0.762: P4.2@28.956,50.097 P4.2@28.956,53.027
  Bottom Layer w0.762: P10.2@28.956,50.097 P10.2@28.956,53.027
  other v1: 28.956,51.562
RESET: P1.3 P7.3 | length 5.9
  Top Layer w0.762: P1.3@22.86,1.837 P1.3@22.86,4.767
  Bottom Layer w0.762: P7.3@22.86,1.837 v1(22.86,3.302) P7.3@22.86,4.767
RF_I: C1.1 J3.1 | length 35.6
  Top Layer w0.32: C1.1 30.805,37.592 cw(c33.345,37.592) 33.345,40.132 39.28,40.132 J3.1 J3.1@58.928,40.132
RF_O1: C2.2 C3.2 J1.1 L1.2 | length 32
  Top Layer w0.3: J1.1 19.28,17.272 26.726,17.272 ccw(c26.726,19.812) 29.266,19.812 29.266,21.684 ; C3.2 29.266,21.684 ; C2.2 29.255,23.557 L1.2 29.266,21.684
RF_O2: C4.2 C5.2 J2.1 L2.2 | length 33.5
  Top Layer w0.3: C5.2@32.23,21.684 31.694,21.684 ; C4.2@32.23,23.557 31.705,23.557 L2.2 31.694,21.684 ; J2.1 J2.1@58.928,17.272 ; J2.1@57.475,17.272 41.68,17.272 34.234,17.272 cw(c34.234,19.812) 31.694,19.812 31.694,21.684
RX_EN: P3.4 P9.4 U1.7 | length 34.7
  Top Layer w0.152: U1.7 32.658,27.757 34.354,29.453 34.621,29.453 v1(34.901,29.733)
  Top Layer w0.762: P3.4@45.72,50.097 P3.4@45.72,53.027
  Bottom Layer w0.152: v1(34.901,29.733) 35.492,30.324 35.492,30.628 41.25,36.386 41.25,47.082 42.941,48.773 44.941,48.773 45.44,49.272 P9.4@45.44,49.766
  Bottom Layer w0.762: P9.4@45.72,50.097 P9.4@45.72,53.027
  other v1: 45.72,51.562
SCL: P4.10 P10.10 | length 5.9
  Top Layer w0.762: P4.10@8.636,50.097 P4.10@8.636,53.027
  Bottom Layer w0.762: P10.10@8.636,50.097 P10.10@8.636,53.027
  other v1: 8.636,51.562
SDA: P4.9 P10.9 | length 5.9
  Top Layer w0.762: P4.9@11.176,50.097 P4.9@11.176,53.027
  Bottom Layer w0.762: P10.9@11.176,50.097 P10.9@11.176,53.027
  other v1: 11.176,51.562
TRX: C1.2 U1.10 | length 1.5
  Top Layer w0.32: U1.10 C1.2
TX_EN: P3.6 P9.6 U1.9 | length 31.6
  Top Layer w0.152: U1.9 31.455,29.677 v1(33.088,31.31)
  Top Layer w0.762: P3.6@40.64,50.097 P3.6@40.64,53.027
  Bottom Layer w0.152: v1(33.088,31.31) 33.102,31.324 35.233,31.324 40.64,36.731 P9.6@40.64,50.097
  Bottom Layer w0.762: P9.6@40.64,50.097 P9.6@40.64,53.027
  other v1: 40.64,51.562
VDD: P1.1 P1.2 P1.4 P5.1 P7.1 P7.2 P7.4 R3.2 | length 40.8
  Top Layer w0.5: P5.1 17.638,8.147 ; P1.1@17.78,4.767 17.78,8.005 17.638,8.147 ; P1.2@20.32,4.767 20.353,4.8 20.353,8.147 ; P1.4@25.4,4.767 25.4,7.236 24.489,8.147 20.353,8.147 ; 17.638,8.147 20.353,8.147
  Top Layer w0.762: P1.1@17.78,1.837 P1.1@17.78,4.767 ; P1.2@20.32,2.032 v1(20.32,3.302) P1.2@20.32,4.767 ; P1.4@25.4,2.032 v1(25.4,3.302) P1.4@25.4,4.962
  Bottom Layer w0.762: P7.1@17.78,1.837 v1(17.78,3.302) P7.1@17.78,4.767 ; P7.2@20.32,1.837 v1(20.32,3.302) P7.2@20.32,4.767 ; P7.4@25.4,1.837 v1(25.4,3.302) P7.4@25.4,4.767
VDD_nRF: C7.2 C8.2 P5.2 R3.1 U1.5 U1.6 | length 49.3
  Top Layer w0.254: U1.5 33.674,26.457 33.706,26.489 33.088,27.107 U1.6 ; 33.69,26.457 C8.2@34.682,26.457 ; C8.2@34.682,26.489 C8.2
  Top Layer w0.381: C8.2 34.873,26.33 v1(36.062,26.33)
  Top Layer w0.5: P5.2 v1(14.6,5.607) 15.635,6.642 R3.1
  Bottom Layer w0.5: v1(14.6,5.607) 17.024,8.031 33.487,8.031 36.062,10.605 v1(36.062,26.33)
pads on no net: Fid1.0 Fid2.0 Fid3.0 J1.0 J2.0 J3.0 P5.0 P11.1 P11.2 P11.3 P11.4 P11.5

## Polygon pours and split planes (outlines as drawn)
GND on Mid-Layer 1 "Mid_Layer_1-GND" (solid, remove dead copper, pour order 7): 0,0 0,54.864 60.96,54.864 60.96,0
GND on Mid-Layer 2 "Mid_Layer_2-GND" (solid, remove dead copper, pour order 10): 0,0 0,54.864 60.96,54.864 60.96,0
GND on Top Layer "Top_Layer-GND" (solid, remove dead copper, pour order 8): 0,0 0,54.864 60.96,54.864 60.96,0
GND on Bottom Layer "Bottom_Layer-GND" (solid, remove dead copper, pour order 6): 0,0 0,54.864 60.96,54.864 60.96,0

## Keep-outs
Keep-Out Layer:
  circle w0.152: c5.08,51.562 r2.4
  circle w0.152: c55.88,8.382 r2.4
  lines w0.254: 0,1.016 ccw(c1.016,1.016) 1.016,0 59.944,0 ccw(c59.944,1.016) 60.96,1.016 60.96,53.848 ccw(c59.944,53.848) 59.944,54.864 1.016,54.864 ccw(c1.016,53.848) 0,53.848 0,1.016

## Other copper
Top Layer:
  region net GND: 30.724,22.693 30.724,23.968 30.424,23.968 30.424,22.693
Mid-Layer 1:
  pour cut-out: 7.285,15.936 7.285,18.608 0.015,18.608 0.015,15.936
  pour cut-out: 53.672,18.608 53.672,15.936 60.942,15.936 60.942,18.608
  pour cut-out: 53.69,41.468 53.69,38.796 60.96,38.796 60.96,41.468
Mid-Layer 2:
  pour cut-out: 7.285,15.936 7.285,18.608 0.015,18.608 0.015,15.936
  pour cut-out: 53.672,18.608 53.672,15.936 60.942,15.936 60.942,18.608
  pour cut-out: 53.69,41.468 53.69,38.796 60.96,38.796 60.96,41.468

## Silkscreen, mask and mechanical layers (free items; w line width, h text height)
Top Overlay:
  drawing of 47 lines, arcs and shapes, not listed
  text "SS" at 26.979,47.124 h1.8 r90
  text "'.PCBNumber'" at 2.042,46.922 h2.03
  text "SCK" at 19.358,46.061 h1.8 r90
  text "GND" at 16.819,45.996 h1.8 r90
  text "MOSI" at 24.439,45.611 h1.8 r90
  text "MISO" at 21.899,45.578 h1.8 r90
  text "'.PCBRevision'" at 2.042,45.398 h1.65
  text "MODE" at 48.823,45.02 h1.8 r90
  text "TX_EN" at 41.18,44.705 h1.8 r90
  text "RX_EN" at 46.26,44.628 h1.8 r90
  text "ANT_SEL" at 43.729,42.897 h1.8 r90
  text "TRX" at 53.48,38.608 h2.03 r90
  text "nRF21540-EK" at 10.846,34.4 h7
  text "ANT2" at 53.48,15.367 h2.03 r90
  text "ANT1" at 8.78,15.285 h2.03 r90
  text "Current measurement" at 0.65,9.873 h2
  text "nRF21" at 1.2,6.332 h1.8
  text "VDD" at 18.343,6.142 h1.8 r90
  text "VDD" at 20.883,6.142 h1.8 r90
  text "VDD" at 25.963,6.142 h1.8 r90
  text "GND" at 31.043,6.142 h1.8 r90
  text "GND" at 33.583,6.142 h1.8 r90
  text "GND" at 1.653,1.287 h1.8
Bottom Overlay:
  text "GND" at 16.819,48.735 h1.8 r90
  text "SCK" at 19.358,48.727 h1.8 r90
  text "MISO" at 21.899,48.727 h1.8 r90
  text "MOSI" at 24.439,48.727 h1.8 r90
  text "SS" at 26.979,48.727 h1.8 r90
  text "TX_EN" at 41.18,48.727 h1.8 r90
  text "ANT_SEL" at 43.729,48.727 h1.8 r90
  text "RX_EN" at 46.26,48.727 h1.8 r90
  text "MODE" at 48.823,48.727 h1.8 r90
  text "GND" at 31.043,8.882 h1.8 r90
  text "GND" at 33.583,8.882 h1.8 r90
  text "VDD" at 18.343,8.801 h1.8 r90
  text "VDD" at 20.883,8.801 h1.8 r90
  text "VDD" at 25.963,8.801 h1.8 r90
Board Outline:
  the board outline again, w0.152
Bottom Assembly:
  drawing of 40 lines, arcs and shapes, not listed
Top Impedance Info:
  lines w0.28: 29.266,24.116 29.835,24.685 ccw(c29.063,25.457) 30.155,25.457 ; 30.805,25.457 ccw(c31.896,25.457) 31.125,24.685 31.694,24.116
  lines w0.3: 3.485,17.272 19.28,17.272 26.726,17.272 ccw(c26.726,19.812) 29.266,19.812 29.266,21.684 ; 28.73,21.684 29.266,21.684 ; 28.73,23.557 29.255,23.557 29.266,23.546 29.266,21.684 ; 32.23,21.684 31.694,21.684 ; 32.23,23.557 31.705,23.557 31.694,23.546 31.694,21.684 ; 58.928,17.272 57.472,17.272 34.234,17.272 cw(c34.234,19.812) 31.694,19.812 31.694,21.684
  lines w0.32: 30.805,29.407 30.805,30.957 ; 30.805,31.527 30.805,37.592 cw(c33.345,37.592) 33.345,40.132 57,40.132
  text "50ohm single ended (coplanar) impedance" at 33.95,24.932 h1.02

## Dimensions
59.944,0 to 59.944,54.864 on Dimensions
0,1.016 to 60.96,1.016 on Dimensions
